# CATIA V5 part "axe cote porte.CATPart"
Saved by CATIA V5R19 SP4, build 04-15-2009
Part number: axe cote porte
Bounding box of the stored display mesh (mm): x 0 to 176.51, y -12.497 to 12.503, z -12.163 to 12.458
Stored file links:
  G:\EU_thinkMotion\CFAO_2010\MMS_groupe1\MMS_groupe1\A reprendre\OK\rdeneffle\axe cote porte.CATPart
  G:\EU_thinkMotion\CFAO_2010\MMS_groupe1\MMS_groupe1\A reprendre\OK\rdeneffle\systeme d'ouverture de porte de voiture.CATProduct
  G:\EU_thinkMotion\CFAO_2010\MMS_groupe1\MMS_groupe1\A reprendre\OK\rdeneffle\Part1.CATPart
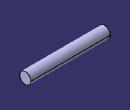
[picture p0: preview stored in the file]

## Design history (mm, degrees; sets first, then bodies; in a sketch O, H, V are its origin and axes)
Body1 (main body)
  Sketch1 on yz-plane, origin (0, 0, 0), H (0, 1, 0), V (0, 0, 1)
    circle A1 centre (0.0034, 0.1475) radius 12.5
    radius A1 = 12.5
  Pad1: profile Sketch1, direction (1, 0, 0), length 176.51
